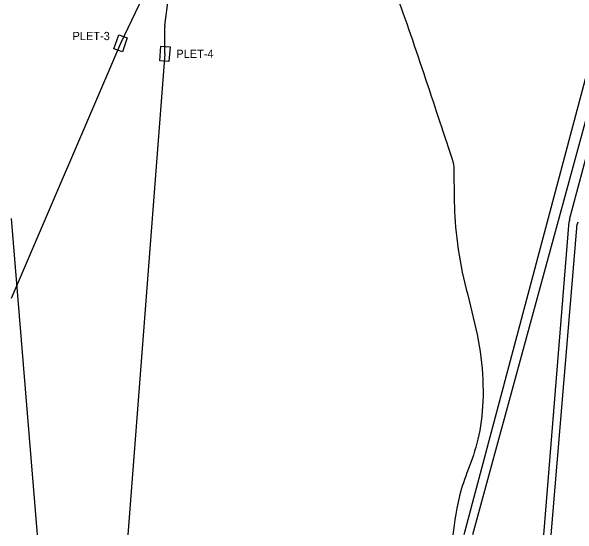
# Model space of a CAD drawing. Extents: x 387828 to 391861, y 7650362 to 7652502.
# Drawn here: x 387828 to 389207, y 7650362 to 7651637 of the extents above; entities that cross this region are included whole.
import ezdxf

# ---------------------------------------------------------------- set-up
doc = ezdxf.new("R2010")
doc.units = 0
for name, color, linetype in [('Batimetria', 7, 'Continuous'), ('Projeto de manifold e PLEM', 7, 'Continuous'), ('Texto dos gasodutos', 7, 'Continuous'), ('Variacoes de flexivel', 7, 'Continuous'), ('Variacoes de rigido', 7, 'Continuous')]:
    doc.layers.add(name, color=color, linetype=linetype)

msp = doc.modelspace()

# ---------------------------------------------------------------- linework, layer by layer
at = {"layer": 'Batimetria'}
msp.add_open_spline([(388468.4, 7652502.5), (388491.3, 7652433.6), (388537.3, 7652291), (388537.3, 7652074.7), (388611, 7652074.7), (388684.6, 7651853.7), (388758.3, 7651706.2), (388831.9, 7651485.2), (388905.6, 7651264.2), (388905.6, 7651264.2), (388905.6, 7651043.2), (388979.2, 7650822.2), (388979.2, 7650601.2), (388914.3, 7650471.2), (388907.1, 7650390.6), (388902.8, 7650362.3)], degree=3, dxfattribs=at)
at = {"layer": 'Projeto de manifold e PLEM'}
for points in [[(388077.6, 7651545.5), (388089.5, 7651579.5), (388110.3, 7651572.2), (388098.5, 7651538.2)], [(388189.4, 7651516.5), (388192.5, 7651552.4), (388214.5, 7651550.5), (388211.5, 7651514.6)]]:
    msp.add_lwpolyline(points, close=True, dxfattribs=at)
at = {"layer": 'Variacoes de flexivel'}
for p, q in [((389262.8, 7651615.6), (388929.3, 7650362.3)), ((389289.2, 7651605.3), (388950.3, 7650362.3)), ((389187, 7651130.1), (389309.8, 7651594.4)), ((389124.5, 7650362.3), (389186.1, 7651124.9)), ((389142.5, 7650362.3), (389205.7, 7651118.4))]:
    msp.add_line(p, q, dxfattribs=at)
msp.add_lwpolyline([(387828.2, 7651132.5), (387891.2, 7650362.3)], dxfattribs=at)
for centre, start, end in [((389216, 7651122.4), 165.1912, 175.382), ((389235.6, 7651115.9), 164.7379, 175.222)]:
    msp.add_arc(centre, 30, start, end, dxfattribs=at)
at = {"layer": 'Variacoes de rigido'}
for p, q in [((388221, 7651826.5), (388094, 7651558.8)), ((388202.2, 7651602.3), (388229.1, 7651828.1)), ((388202, 7651533.5), (388202, 7651598.7)), ((388094, 7651558.8), (387828.2, 7650937.5)), ((388202, 7651533.5), (388112.1, 7650362.3))]:
    msp.add_line(p, q, dxfattribs=at)
msp.add_arc((388232, 7651598.7), 30, 173.2142, 180, dxfattribs=at)

# ---------------------------------------------------------------- texts
at = {"layer": 'Texto dos gasodutos'}
for s, p in [('PLET-3', (387977.2, 7651566.9)), ('PLET-4', (388229.7, 7651523.6))]:
    msp.add_text(s, height=20, dxfattribs=at).set_placement(p)

doc.saveas('drawing.dxf')
